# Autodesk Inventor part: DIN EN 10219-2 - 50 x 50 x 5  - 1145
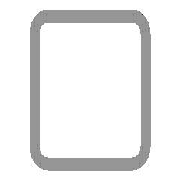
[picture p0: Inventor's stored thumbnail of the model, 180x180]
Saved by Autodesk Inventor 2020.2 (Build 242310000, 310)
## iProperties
Created: 2019-01
Part Number: DIN EN 10219-2 - 50 x 50 x 5  - 1145
Material: Stahl, weich
Description: Kaltgeformte, geschweißte Baustahl-Hohlprofile aus unlegiertem Feinkorn-Baustahl
Document SubType Name: Modeling
Standard: DIN
Designer: lutzd
Standard Revision: 2006-07
Standards Organization: DIN
Language: de-DE
Size Designation: 50 x 50 x 5
Categories: <MemberInstance><Categories><Category DisplayName="Profile" InternalName="089c4875-fa83-4c05-b084-43b9cc11f5ed" Mnemonic="GRDR"><CategoryParameter DisplayName="
Stock Number: 50 x 50 x 5
Mass: 7510.76 g
Surface Area: 3843.85 cm^2
Volume: 956.784 cm^3
Density: 7.85 g/cm^3
Appearance: Semi-Polished(8)
_CCFamilyMember: 16
_CCFamilyDisplayName: DIN EN 10219-2 (Quadratisches Hohlprofil - Kaltgeformt) - Kaltgeformte, geschweißte Baustahl-Hohlprofile aus unlegiertem Feinkorn-Baustahl
_FrameMemberDoc: Frame Member File
_Version: 15.0.0
_GetPNFromCC: 1
G_L: 1145,000 mm
G_W: 50,000 mm
G_H: 50,000 mm
Mass: 7,511 kg
VLT_Material: Stahl, weich
+B474FADB-D98D-46AF-9457-FBB454D8E573+SCHNITTDETAIL1: Schnittwinkel 90,00 grd
Dimensions: 50x50x1145 mm
+1FCEA8DF-9951-4D73-B98F-835B59C89551+SCHNITTDETAIL2: Schnittwinkel 90,00 grd
IsCustomPart: 1
Author: lutzd
Revision Number: -
Title: Kaltgeformte, geschweißte Baustahl-Hohlprofile aus unlegiertem Feinkorn-Baustahl
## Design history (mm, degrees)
node "Startebene"
node "Endebene"
sketch "Skizze"
  geometry: L1 (-25, -15)-(-25, 15); L2 (-15, 25)-(15, 25); L3 (25, 15)-(25, -15); L4 (15, -25)-(-15, -25); L5 (-15, 20)-(15, 20); L6 (20, 15)-(20, -15); L7 (15, -20)-(-15, -20); L8 (-20, -15)-(-20, 15); L9 (0, 37.899)-(0, -37.899) reference; L10 (-37.899, 0)-(37.899, 0) reference; A1 r 10 centre (-15, -15) between (-25, -15) and (-15, -25); A2 r 10 centre (-15, 15) between (-15, 25) and (-25, 15); A3 r 10 centre (15, 15) between (25, 15) and (15, 25); A4 r 10 centre (15, -15) between (15, -25) and (25, -15); A5 r 5 centre (-15, 15) between (-15, 20) and (-20, 15); A6 r 5 centre (15, 15) between (20, 15) and (15, 20); A7 r 5 centre (15, -15) between (15, -20) and (20, -15); A8 r 5 centre (-15, -15) between (-20, -15) and (-15, -20)
  constraints: 16 end point, 16 point on circle, 8 centre point, 8 tangent, 4 parallel, 3 equal radius, 2 perpendicular, 7 other
  dimensions: "d7" = 10 radius of A1 (= G_IR); "d10" = 50 distance between parallel lines of L2 L4 (= G_H); "d11" = 50 distance between parallel lines of L1 L3 (= G_W); "d12" = 5 distance between parallel lines of L3 L6 (= G_T); "d15" = 25 distance between parallel lines of L2 L10 (= 0.5 x d10); "d16" = 25 distance between parallel lines of L9 L3 (= 0.5 x d11)
extrude "Körper" new body sketch "Skizze" stored distance "d3" = 1145 (= G_L); taper "d4" = 0 deg
node "Driven Length"
  sketch "Sketch3"
    geometry: L1 (0, 0)-(10, 0) reference
    constraints: 2 end point, 1 horizontal
  workplane "Work Plane3"
  sketch "Sketch4"
    geometry: L1 (-2, 35)-(12, 35) reference; L2 (-2, 1180)-(12, 1180) reference
    dimensions: "d18" = 1145 distance between parallel lines of L1 L2 (derived)
workplane "Arbeitsebene4"
feature "Trennen1"
workplane "Arbeitsebene5"
feature "Trennen2"
body "Solid1"
other parameters: "G_W" = 50 [user parameter; used in 1 equation term], "G_H" = 50 [user parameter; used in 1 equation term], "G_T" = 5 [user parameter; used in 1 equation term], "G_IR" = 10 [user parameter; used in 1 equation term], "G_L" = 1145 (= d18) [user parameter; used in 1 equation term], "G_OFFSET_START" = -35 [user parameter; used in 1 equation term], "d13" = 35 (= -G_OFFSET_START), "d17" = 90 deg
